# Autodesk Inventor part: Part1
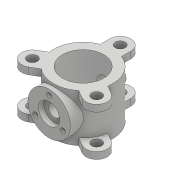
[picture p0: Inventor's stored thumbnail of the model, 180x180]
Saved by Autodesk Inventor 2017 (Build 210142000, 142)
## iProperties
Created: 2016-06
Part Number: Part1
Material: Generic
Document SubType Name: Modeling
Designer: Sandeep
Density: 1 g/cm^3
Appearance: Default
Author: Sandeep
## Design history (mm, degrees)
sketch "Sketch1"
  geometry: C1 r 140 at (0, 0); C2 r 97 at (0, 0); 1 further point
  constraints: 2 centre point, 2 coincident
  dimensions: "d0" = 194 diameter of C2; "d1" = 280 diameter of C1
extrude "Extrusion1" new body sketch "Sketch1" stored distance "d2" = 225; taper "d3" = 0 deg
workplane "Work Plane1"
sketch "Sketch2"
  geometry: C1 r 100 at (0, 0); 1 further point
  constraints: 1 centre point, 1 coincident
  dimensions: "d5" = 200 diameter of C1
extrude "Extrusion2" join sketch "Sketch2" stored distance "d6" = 225; taper "d7" = 0 deg
workplane "Work Plane2"
sketch "Sketch3"
  geometry: C1 r 37.5 at (0, 0); 1 further point
  constraints: 1 centre point, 1 coincident
  dimensions: "d9" = 75 diameter of C1
extrude "Extrusion3" join sketch "Sketch3" stored distance "d10" = 225; taper "d11" = 0 deg
sketch "Sketch4" dims "d12" = 150
  geometry: 3 further points
  constraints: 1 coincident, 1 vertical alignment, 2 other
hole "Hole1" sketch "Sketch4" at (0, 75) diameter "d13" = 24; stored, may be unused: countersink angle "d17" = 90 deg, drill point angle "d19" = 0 deg; dims "d14" = 6, "d15" = 4, "d16" = 2, "d18" = 15
pattern_circular "Circular Pattern1" dims angle "d21" = 360 deg
hole "Hole2" diameter "d25" = 56; stored, may be unused: countersink angle "d29" = 90 deg, drill point angle "d31" = 0 deg; dims "d26" = 6, "d27" = 100, "d28" = 25, "d30" = 310, "d42" = 10, "d43" = 10
sketch "Sketch5"
  geometry: L1 (-50, 130.767)-(-50, 175); L2 (50, 175)-(50, 130.767); L3 (0, 0)-(150.852, 0); L4 (0, 0)-(0, 85.044); C1 r 23.5 at (0, 175); A1 r 140 centre (0, 0) between (-50, 130.767) and (50, 130.767) reference; A2 r 50 centre (0, 175) between (50, 175) and (-50, 175); A3 r 140 centre (0, 0) between (50, 130.767) and (-50, 130.767); 1 further point
  constraints: 8 end point, 6 point on circle, 3 centre point, 3 vertical, 2 coincident, 2 tangent, 1 concentric, 1 horizontal, 1 other
  dimensions: "d34" = 50 radius of A2; "d35" = 175 distance of A2.centre point (0, 0); "d36" = 47 diameter of C1
extrude "Extrusion4" join sketch "Sketch5" distance "d37" = 32; taper "d38" = 0 deg
pattern_circular "Circular Pattern2" dims angle "d40" = 360 deg
mirror "Mirror2"
body "Solid1"
other parameters: "d8" = 325
